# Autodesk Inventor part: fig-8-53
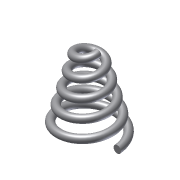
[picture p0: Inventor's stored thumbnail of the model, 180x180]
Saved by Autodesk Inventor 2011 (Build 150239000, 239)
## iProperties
Shininess: 77.0
Length Units: 11269
Angle Units: 11279
Time Units: 11290
Mass Units: 11283
Length Display Precision: 3
Angle Display Precision: 2
Created: 2002-01
Part Number: fig-8-53
Document SubType Name: Modeling
Designer: CADSoft
Density: 1 g/cm^3
Density: 0.0
Volumn: 0.0
Area: 0.0
PropertySet Name: Model Information
Control State: 0
Master: False
Checked Out: False
Author: CADSoft
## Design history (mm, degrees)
sketch "Sketch2"
  geometry: C1 r 2.5 at (-19.895, -0.092)
  constraints: 1 centre point
  dimensions: "d0" = 5 diameter of C1
coil "Coil5" sketch "Sketch2" pitch "d35" = 10; turns "d37" = 5; dims "d36" = 10, "d38" = -15 deg, angle "d39" = 90 deg, angle "d40" = 90 deg, "d41" = 0, "d42" = 0
body "Solid1"
